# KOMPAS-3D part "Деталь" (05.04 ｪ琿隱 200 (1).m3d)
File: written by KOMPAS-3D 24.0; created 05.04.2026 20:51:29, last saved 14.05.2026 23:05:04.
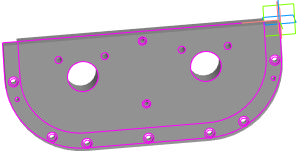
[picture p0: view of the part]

Document properties: Автор: taras; Полное имя файла: E:\test_kompas\all_v22\05.04 крышка200 (1).m3d

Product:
- Part/product: Деталь
    Масса: 19.948382

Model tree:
1. Эскиз:3
2. Элемент выдавливания:24
     Расстояние 1 = 20
3. Элемент выдавливания:25
     Расстояние 1 = -20
4. Эскиз:4  (with: Грань.Элемент выдавливания:24, Вершина.Элемент выдавливания:24)
5. Элемент выдавливания:26
     Расстояние 1 = -40
6. Элемент выдавливания:27
     Расстояние 1 = -40
7. Элемент выдавливания:28
     Расстояние 2 = 40
8. Элемент выдавливания:29
     Расстояние 2 = 11
9. Элемент выдавливания:30
     Расстояние 2 = 20
10. Элемент выдавливания:31
     Расстояние 2 = 20
11. Элемент выдавливания:32
     Расстояние 2 = 30
12. Элемент выдавливания:35
     Расстояние 2 = 20
13. Элемент выдавливания:36
     Расстояние 2 = 10
14. Элемент выдавливания:37
     Расстояние 2 = 40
